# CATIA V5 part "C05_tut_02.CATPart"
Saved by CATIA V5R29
Part number: Part1
Bounding box of the stored display mesh (mm): x -20 to 5, y -42.072 to 42.072, z 0 to 101.82
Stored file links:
  D:\Abhinav\2019\3rd Session\CATIA V5 2019\RESOURCES\CATIA_RESOURCES\Tutorial Files\Tutorials\Tutorials\c05_catia_v5_6r2018_tut\c05_catia_v5_6r2018_tut\c05_catia_v5_6r2018_tut\C05_tut_02.CATPart
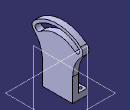
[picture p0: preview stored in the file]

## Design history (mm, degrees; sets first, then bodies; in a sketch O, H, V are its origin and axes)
Body1 (main body)
  Sketch1 on yz-plane, origin (0, 0, 0), H (0, 1, 0), V (0, 0, 1)
    point P1 (-25, 0)
    line L1 (-25, 0) -> (25, 0)
    point P2 (25, 0)
    line L2 (-25, 0) -> (-25, 38.3145)
    point P3 (-25, 38.3145)
    arc A1 centre (0, 42) radius 60 from (38.5673, 87.9627) to (-38.5673, 87.9627) ccw
    point P4 (0, 42)
    axis line L3 (0, 42) -> (-54.0665, 106.434)
    point P5 (-54.0665, 106.434)
    point P6 (54.0665, 106.434)
    point P7 (0, 42)
    construction line L4 (0, 42) -> (54.0665, 106.434)
    point P8 (-38.5673, 87.9627)
    point P9 (38.5673, 87.9627)
    arc A2 centre (-32.1394, 80.3022) radius 10 from (-38.5673, 87.9627) to (-39.2828, 73.3043) ccw
    point P10 (-32.1394, 80.3022)
    arc A3 centre (32.1394, 80.3022) radius 10 from (38.5673, 87.9627) to (39.2828, 73.3043) cw
    arc A4 centre (-75, 38.3145) radius 50 from (-25, 38.3145) to (-39.2828, 73.3043) ccw
    arc A5 centre (75, 38.3145) radius 50 from (25, 38.3145) to (39.2828, 73.3043) cw
    point P14 (25, 38.3145)
    point P15 (25, 0)
    line L5 (25, 0) -> (25, 38.3145)
    point P17 (25, 38.3145)
    length L1 = 50
    angle L4 L3 = 80
    radius A1 = 60
    radius A2 = 10
    radius A5 = 50
    distance P4 L1 = 42
    coincidence: P1 H, P4 V, L3 P8, L4 P9, P10 L3, L5 P17, P2 P15, P14 P17
    horizontal: L1 H
    symmetry: P2 P1 V, P5 P6 V, P4 P7 V, L3 L4 V, A2 A3 V, A4 A5 V, P3 P14 V, P1 P15 V, L2 L5 V
    vertical: L2 V
    tangency: A2 A1, A4 A2, A4 L2, A5 A3, L5 A5
  Pad1: profile Sketch1, direction (1, 0, 0), length 5, mirrored extent
  Sketch2 on start face of Pad1, origin (-5, 0, 0), H (0, -1, 0), V (0, 0, 1)
    construction arc A1 centre (0, 42) radius 50 from (32.1394, 80.3022) to (-32.1394, 80.3022) ccw
    point P1 (0, 42)
    arc A2 centre (32.1394, 80.3022) radius 5 from (35.3533, 84.1324) to (28.9254, 76.472) cw
    arc A3 centre (-32.1394, 80.3022) radius 5 from (-28.9254, 76.472) to (-35.3533, 84.1324) cw
    arc A4 centre (0, 42) radius 45 from (28.9254, 76.472) to (-28.9254, 76.472) ccw
    arc A5 centre (0, 42) radius 55 from (-35.3533, 84.1324) to (35.3533, 84.1324) cw
    construction line L1 (-32.1394, 80.3022) -> (0, 42)
    construction line L2 (0, 42) -> (32.1394, 80.3022)
    radius A3 = 5
    radius A1 = 50
    angle L2 L1 = 80
    angle L2 V = 40
    distance P1 H = 42
    coincidence: P1 V
    tangency: A4 A3, A3 A5, A5 A2, A2 A4
    concentricity: A4 P1, A5 P1
  Pocket1: profile Sketch2, direction (1, 0, 0), through (limit type 6)
  Sketch3 on start face of Pad1, origin (-5, 0, 0), H (0, 1, 0), V (0, 0, 1)
    line L1 (-25, 10) -> (25, 10)
    line L2 (25, 10) -> (25, 0)
    line L3 (25, 0) -> (-25, 0)
    line L4 (-25, 0) -> (-25, 10)
    point P3 (25, 0)
    reference projected line E1 (25, 0) -> (25, 38.3145) from edge [face of Pad1 from Sketch1.L5 | end face of Pad1]
    reference projected line E2 (-25, 38.3145) -> (-25, 0) from edge [face of Pad1 from Sketch1.L2 | end face of Pad1]
    length L2 = 10
    horizontal: L1 H, L3 H
    vertical: L2 V, L4 V
    coincidence: P3 H, L2 E1, L4 E2
  Pad2: profile Sketch3, direction (-1, 0, 0), length 15
  Sketch4 on face of Pad2 from Sketch3.L1, origin (0, 0, 10), H (1, 0, 0), V (0, 1, 0)
    circle A1 centre (-14, 19) radius 2.5
    point P1 (-14, 19)
    reference projected line E1 (-5, 25) -> (-20, 25) from edge [face of Pad2 | face of Pad2 from Sketch3.L1]
    reference projected line E2 (-20, 25) -> (-20, -25) from edge [end face of Pad2 | face of Pad2 from Sketch3.L1]
    circle A2 centre (-14, -19) radius 2.5
    radius A1 = 2.5
    distance E1 P1 = 6
    distance E2 P1 = 6
    symmetry: A1 A2 H
  Pocket2: profile Sketch4, direction (0, 0, -1), through (limit type 3)
  Sketch5 on start face of Pad1, origin (-5, 0, 0), H (0, -1, 0), V (0, 0, 1)
    circle A1 centre (0, 42) radius 11
    point P1 (0, 42)
    circle A2 centre (0, 42) radius 4
    reference projected line E1 (25, 0) -> (-25, 0) from edge [end face of Pad2 | face of Pad2]
    radius A1 = 11
    radius A2 = 4
    distance P1 E1 = 42
    coincidence: P1 V
  Pad3: profile Sketch5, direction (-1, 0, 0), length 9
